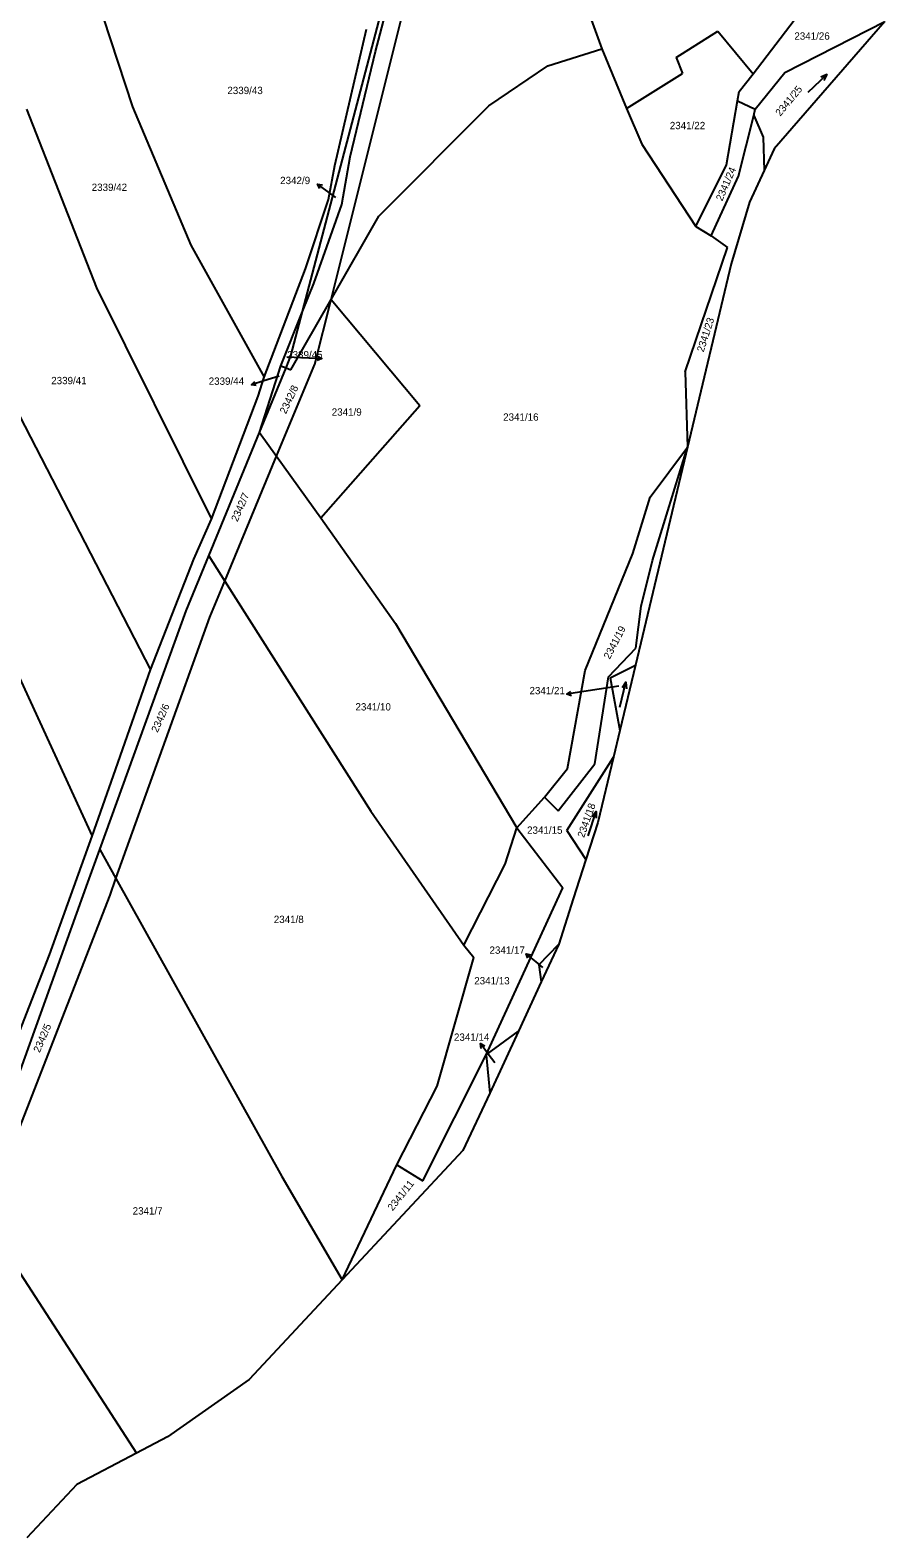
# Model space of a CAD drawing. Extents: x -785744 to -782822, y -1067550 to -1063910.
# Drawn here: x -784470.5 to -784272.2, y -1067464.2 to -1067114 of the extents above; entities that cross this region are included whole.
import ezdxf

# ---------------------------------------------------------------- set-up
doc = ezdxf.new("R2010")
doc.units = 0
for name, color, linetype in [('Hranice obce', 7, 'Continuous'), ('Hranice parcel', 7, 'Continuous'), ('Parcelní čísla', 7, 'Continuous'), ('Pop_ČP_popisy', 7, 'Continuous'), ('Značky kultur', 7, 'Continuous')]:
    doc.layers.add(name, color=color, linetype=linetype)

msp = doc.modelspace()

# ---------------------------------------------------------------- linework, layer by layer
at = {"layer": 'Hranice obce'}
msp.add_lwpolyline([(-784272.17, -1067112.02), (-784297.86, -1067141.59), (-784300.2, -1067146.65), (-784303.58, -1067153.98), (-784307.85, -1067168.29), (-784318, -1067210.87), (-784330.08, -1067261.53), (-784333.69, -1067276.67), (-784335.16, -1067282.84), (-784338.79, -1067298.04), (-784341.55, -1067306.65), (-784344.48, -1067315.81), (-784347.85, -1067326.32), (-784351.91, -1067335.07), (-784357.21, -1067346.5), (-784363.89, -1067360.89), (-784370.09, -1067374.26), (-784398.11, -1067404.29), (-784419.73, -1067427.45), (-784438.64, -1067440.73), (-784445.9, -1067444.56), (-784459.68, -1067451.82), (-784471.33, -1067464.19)], dxfattribs=at)
at = {"layer": 'Hranice parcel'}
for points in [[(-784357.96, -1067062.82), (-784337.85, -1067118.35)], [(-784458.71, -1067095.46), (-784446.79, -1067131.82)], [(-784407.31, -1067179.37), (-784386.92, -1067101.67)], [(-784400.72, -1067176.61), (-784382.1, -1067102.21)], [(-784390.43, -1067118.96), (-784386.34, -1067103.66)], [(-784302.7, -1067124.16), (-784288.92, -1067106.03)], [(-784399.83, -1067145.44), (-784392.47, -1067113.81)], [(-784320.61, -1067120.41), (-784310.97, -1067114.23)], [(-784310.97, -1067114.23), (-784302.7, -1067124.16)], [(-784295.41, -1067123.82), (-784272.17, -1067112.02)], [(-784350.39, -1067122.29), (-784337.85, -1067118.35)], [(-784337.85, -1067118.35), (-784332.14, -1067132.24)], [(-784396.25, -1067143.43), (-784390.43, -1067118.96)], [(-784320.61, -1067120.41), (-784319.1, -1067124.07)], [(-784364.08, -1067131.63), (-784350.39, -1067122.29)], [(-784332.14, -1067132.24), (-784319.1, -1067124.07)], [(-784305.98, -1067128.29), (-784302.7, -1067124.16)], [(-784302.25, -1067132.39), (-784295.41, -1067123.82)], [(-784306.36, -1067130.46), (-784305.98, -1067128.29)], [(-784471.41, -1067132.38), (-784455.14, -1067173.87)], [(-784446.79, -1067131.82), (-784433.24, -1067163.96)], [(-784389.59, -1067157.25), (-784364.08, -1067131.63)], [(-784332.14, -1067132.24), (-784328.61, -1067140.49)], [(-784308.92, -1067145.32), (-784306.36, -1067130.46)], [(-784306.36, -1067130.46), (-784302.25, -1067132.39)], [(-784302.61, -1067133.85), (-784302.25, -1067132.39)], [(-784306.12, -1067147.97), (-784302.61, -1067133.85)], [(-784302.61, -1067133.85), (-784300.39, -1067138.87)], [(-784300.39, -1067138.87), (-784300.2, -1067146.65)], [(-784328.61, -1067140.49), (-784316.03, -1067159.64)], [(-784401.29, -1067153.35), (-784399.83, -1067145.44)], [(-784398.2, -1067154.52), (-784396.25, -1067143.43)], [(-784316.03, -1067159.64), (-784308.92, -1067145.32)], [(-784312.51, -1067161.76), (-784306.12, -1067147.97)], [(-784406.67, -1067169.42), (-784401.29, -1067153.35)], [(-784404.67, -1067172.83), (-784398.2, -1067154.52)], [(-784400.72, -1067176.61), (-784389.59, -1067157.25)], [(-784316.03, -1067159.64), (-784312.51, -1067161.76)], [(-784433.24, -1067163.96), (-784416.23, -1067194.64)], [(-784312.51, -1067161.76), (-784308.7, -1067164.53)], [(-784318.55, -1067193.39), (-784308.7, -1067164.53)], [(-784416.23, -1067194.64), (-784406.67, -1067169.42)], [(-784455.14, -1067173.87), (-784428.49, -1067227.61)], [(-784407.31, -1067179.37), (-784404.67, -1067172.83)], [(-784410.08, -1067192.9), (-784400.72, -1067176.61)], [(-784404.47, -1067191.6), (-784400.72, -1067176.61)], [(-784400.72, -1067176.61), (-784380.08, -1067201.22)], [(-784412.4, -1067191.96), (-784407.31, -1067179.37)], [(-784410.01, -1067189.65), (-784407.31, -1067179.37)], [(-784417.32, -1067207.45), (-784412.4, -1067191.96)], [(-784413.34, -1067213), (-784404.47, -1067191.6)], [(-784412.4, -1067191.96), (-784411.16, -1067192.46)], [(-784411.16, -1067192.46), (-784410.01, -1067189.65)], [(-784417.59, -1067199.06), (-784416.23, -1067194.64)], [(-784417.32, -1067207.45), (-784411.16, -1067192.46)], [(-784411.16, -1067192.46), (-784410.08, -1067192.9)], [(-784318.55, -1067193.39), (-784318, -1067210.87)], [(-784475.54, -1067198.64), (-784442.61, -1067262.6)], [(-784428.49, -1067227.61), (-784417.59, -1067199.06)], [(-784403.08, -1067227.3), (-784380.08, -1067201.22)], [(-784429.1, -1067236.14), (-784417.32, -1067207.45)], [(-784417.32, -1067207.45), (-784413.34, -1067213)], [(-784425.37, -1067242.02), (-784413.34, -1067213)], [(-784413.34, -1067213), (-784403.08, -1067227.3)], [(-784326.6, -1067222.49), (-784318, -1067210.87)], [(-784326.08, -1067237.18), (-784318, -1067210.87)], [(-784330.63, -1067235.58), (-784326.6, -1067222.49)], [(-784491.35, -1067224.68), (-784456.19, -1067301.23)], [(-784432.54, -1067236.88), (-784428.49, -1067227.61)], [(-784403.08, -1067227.3), (-784385.72, -1067251.84)], [(-784442.61, -1067262.6), (-784432.54, -1067236.88)], [(-784434.35, -1067248.92), (-784429.1, -1067236.14)], [(-784429.1, -1067236.14), (-784425.37, -1067242.02)], [(-784341.76, -1067262.77), (-784330.63, -1067235.58)], [(-784328.72, -1067247.84), (-784326.08, -1067237.18)], [(-784428.83, -1067250.37), (-784425.37, -1067242.02)], [(-784425.37, -1067242.02), (-784391.45, -1067295.41)], [(-784330, -1067257.58), (-784328.72, -1067247.84)], [(-784454.4, -1067304.33), (-784434.35, -1067248.92)], [(-784450.63, -1067311.09), (-784428.83, -1067250.37)], [(-784385.72, -1067251.84), (-784357.6, -1067299.31)], [(-784336.33, -1067264.18), (-784330, -1067257.58)], [(-784335.92, -1067264.42), (-784330.08, -1067261.53)], [(-784451.21, -1067287.13), (-784442.61, -1067262.6)], [(-784345.8, -1067285.48), (-784341.76, -1067262.77)], [(-784339.52, -1067284.43), (-784336.33, -1067264.18)], [(-784335.92, -1067264.42), (-784333.69, -1067276.67)], [(-784346.01, -1067299.9), (-784335.16, -1067282.84)], [(-784351.15, -1067292.15), (-784345.8, -1067285.48)], [(-784348.01, -1067295.3), (-784339.52, -1067284.43)], [(-784456.19, -1067301.23), (-784451.21, -1067287.13)], [(-784357.6, -1067299.31), (-784351.15, -1067292.15)], [(-784351.15, -1067292.15), (-784348.01, -1067295.3)], [(-784391.45, -1067295.41), (-784369.9, -1067326.54)], [(-784360.31, -1067307.72), (-784357.6, -1067299.31)], [(-784357.6, -1067299.31), (-784346.94, -1067313.23)], [(-784346.01, -1067299.9), (-784341.55, -1067306.65)], [(-784466.1, -1067328.81), (-784456.19, -1067301.23)], [(-784457.18, -1067312.02), (-784454.4, -1067304.33)], [(-784454.4, -1067304.33), (-784450.63, -1067311.09)], [(-784452.01, -1067314.95), (-784450.63, -1067311.09)], [(-784450.63, -1067311.09), (-784412.1, -1067380.23)], [(-784369.9, -1067326.54), (-784360.31, -1067307.72)], [(-784483.81, -1067385.97), (-784457.18, -1067312.02)], [(-784364.67, -1067352.04), (-784346.94, -1067313.23)], [(-784481.23, -1067389.95), (-784452.01, -1067314.95)], [(-784369.9, -1067326.54), (-784367.58, -1067329.41)], [(-784352.49, -1067331.13), (-784347.85, -1067326.32)], [(-784486.47, -1067381.01), (-784466.1, -1067328.81)], [(-784376.09, -1067359.25), (-784367.58, -1067329.41)], [(-784352.49, -1067331.13), (-784351.91, -1067335.07)], [(-784364.67, -1067352.04), (-784357.21, -1067346.5)], [(-784379.39, -1067381.31), (-784364.67, -1067352.04)], [(-784364.67, -1067352.04), (-784363.89, -1067360.89)], [(-784385.44, -1067377.58), (-784376.09, -1067359.25)], [(-784398.11, -1067404.29), (-784385.44, -1067377.58)], [(-784385.44, -1067377.58), (-784379.39, -1067381.31)], [(-784412.1, -1067380.23), (-784398.11, -1067404.29)], [(-784481.23, -1067389.95), (-784445.9, -1067444.56)]]:
    msp.add_lwpolyline(points, dxfattribs=at)
at = {"layer": 'Pop_ČP_popisy'}
for p, q in [((-784401.4, -1067151.54), (-784403.83, -1067149.78)), ((-784405.88, -1067190.12), (-784402.88, -1067190.26)), ((-784416.32, -1067195.5), (-784419.18, -1067196.39)), ((-784343.01, -1067267.79), (-784345.97, -1067268.26)), ((-784353.13, -1067330.44), (-784355.45, -1067328.54)), ((-784364.26, -1067351.82), (-784366.04, -1067349.41))]:
    msp.add_line(p, q, dxfattribs=at)
for points in [[(-784403.31, -1067150.77), (-784403.83, -1067149.78), (-784402.73, -1067149.96)], [(-784399.59, -1067152.85), (-784401.4, -1067151.54)], [(-784410.96, -1067189.89), (-784405.88, -1067190.12)], [(-784403.86, -1067189.71), (-784402.88, -1067190.26), (-784403.9, -1067190.71)], [(-784418.08, -1067196.57), (-784419.18, -1067196.39), (-784418.38, -1067195.62)], [(-784412.75, -1067194.39), (-784416.32, -1067195.5)], [(-784344.91, -1067268.6), (-784345.97, -1067268.26), (-784345.06, -1067267.61)], [(-784333.94, -1067266.35), (-784343.01, -1067267.79)], [(-784355, -1067329.56), (-784355.45, -1067328.54), (-784354.36, -1067328.79)], [(-784351.59, -1067331.69), (-784353.13, -1067330.44)], [(-784365.85, -1067350.51), (-784366.04, -1067349.41), (-784365.05, -1067349.91)], [(-784362.72, -1067353.9), (-784364.26, -1067351.82)]]:
    msp.add_lwpolyline(points, dxfattribs=at)
at = {"layer": 'Značky kultur'}
for points in [[(-784289.95, -1067128.45), (-784285.63, -1067124.29), (-784287.06, -1067124.97)], [(-784285.63, -1067124.29), (-784286.36, -1067125.69)], [(-784333.68, -1067271.26), (-784332.32, -1067265.42), (-784333.14, -1067266.77)], [(-784332.32, -1067265.42), (-784332.17, -1067266.99)], [(-784341.04, -1067301.18), (-784339.2, -1067295.46), (-784340.14, -1067296.74)], [(-784339.2, -1067295.46), (-784339.19, -1067297.04)]]:
    msp.add_lwpolyline(points, dxfattribs=at)

# ---------------------------------------------------------------- texts
at = {"layer": 'Parcelní čísla'}
for s, height, p in [('2341/26', 1.7, (-784293.17, -1067116.23)), ('2339/43', 1.7, (-784424.78, -1067128.87)), ('2341/22', 1.7, (-784322.08, -1067137.02)), ('2339/42', 1.7, (-784456.27, -1067151.36)), ('2342/9', 0.1, (-784399.59, -1067152.85)), ('2339/45', 0.1, (-784410.96, -1067189.89)), ('2339/41', 1.7, (-784465.66, -1067196.25)), ('2339/44', 0.1, (-784412.75, -1067194.39)), ('2341/9', 1.7, (-784400.55, -1067203.56)), ('2341/16', 1.7, (-784360.76, -1067204.73)), ('2341/21', 0.1, (-784333.94, -1067266.35)), ('2341/10', 1.7, (-784395.04, -1067272.03)), ('2341/15', 1.7, (-784355.21, -1067300.67)), ('2341/8', 1.7, (-784414, -1067321.39)), ('2341/17', 0.1, (-784351.59, -1067331.69)), ('2341/13', 1.7, (-784367.47, -1067335.65)), ('2341/14', 0.1, (-784362.72, -1067353.9)), ('2341/7', 1.7, (-784446.76, -1067389.1))]:
    msp.add_text(s, height=height, dxfattribs=at).set_placement(p)
for s, rotation, p in [('2341/25', 50.4206, (-784296.43, -1067134.14)), ('2341/24', 66.6264, (-784309.91, -1067153.84)), ('2341/23', 72.0935, (-784314.25, -1067188.93)), ('2342/8', 64.8599, (-784411.19, -1067203.29)), ('2342/7', 66.4889, (-784422.42, -1067228.31)), ('2341/19', 62.4438, (-784336.03, -1067260.25)), ('2342/6', 65.9216, (-784440.97, -1067277.27)), ('2341/18', 70.5971, (-784341.99, -1067301.69)), ('2342/5', 66.526, (-784468.35, -1067351.63)), ('2341/11', 51.5901, (-784386.42, -1067388.39))]:
    msp.add_text(s, height=1.7, rotation=rotation, dxfattribs=at).set_placement(p)
at = {"layer": 'Pop_ČP_popisy'}
for s, p in [('2342/9', (-784412.52, -1067149.78)), ('2339/45', (-784410.89, -1067190.26)), ('2339/44', (-784429.11, -1067196.39)), ('2341/21', (-784354.65, -1067268.26)), ('2341/17', (-784363.93, -1067328.54)), ('2341/14', (-784372.18, -1067348.75))]:
    msp.add_text(s, height=1.7, dxfattribs=at).set_placement(p)

doc.saveas('drawing.dxf')
